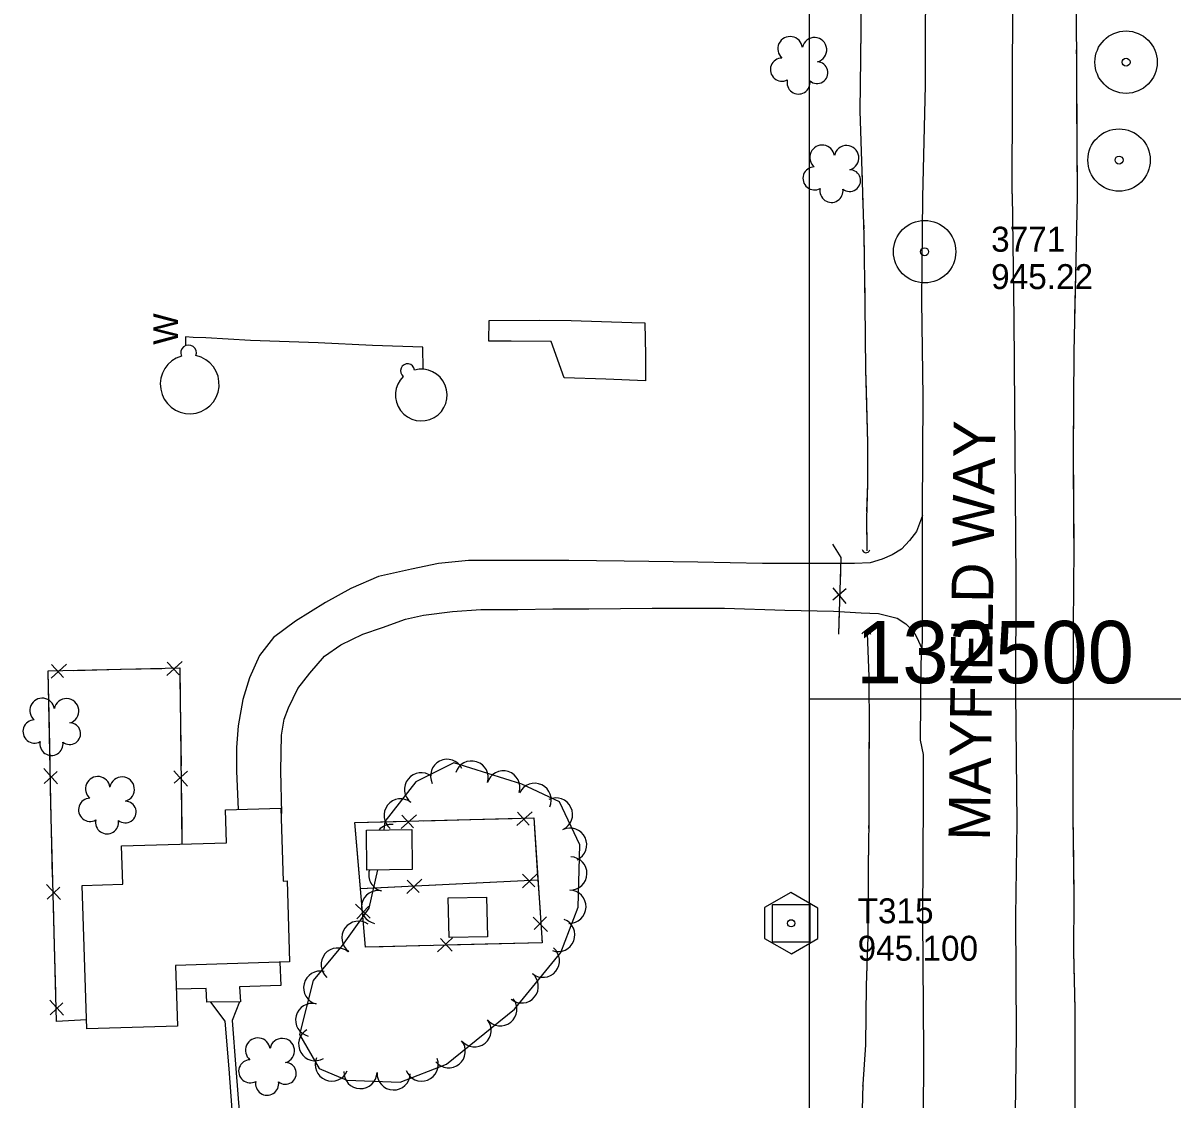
# Model space of a CAD drawing. Extents: x 353423 to 364002, y 127000 to 201942.
# Drawn here: x 359810.7 to 360087.2, y 132403.7 to 132662.6 of the extents above; entities that cross this region are included whole.
import ezdxf

# ---------------------------------------------------------------- set-up
doc = ezdxf.new("R2010")
doc.units = 0
for name, color, linetype in [('E_BMGRD', 7, 'Continuous'), ('E_DTM_SlopeBottom', 7, 'Continuous'), ('E_DTM_SlopeTop', 7, 'Continuous'), ('E_FEN_Generic', 7, 'Continuous'), ('E_LAND_TreeLine', 7, 'Continuous'), ('E_MISCPROP', 7, 'Continuous'), ('E_RDWY_AsphConc', 7, 'Continuous'), ('E_RW_IP', 7, 'Continuous'), ('E_STRUCT_WingWall', 7, 'Continuous'), ('E_WTR_FlowLine', 7, 'Continuous')]:
    doc.layers.add(name, color=color, linetype=linetype)

msp = doc.modelspace()

# ---------------------------------------------------------------- linework, layer by layer
at = {"layer": 'E_BMGRD'}
for points in [[(359989.15, 132449.77), (359989.15, 132442.38), (359995.61, 132438.65), (360002, 132442.32), (360002, 132449.65), (359995.48, 132453.38)], [(359989.15, 132449.77), (359989.15, 132442.38), (359995.61, 132438.65), (360002, 132442.32), (360002, 132449.65), (359995.48, 132453.38)], [(359991.06, 132441.51), (359991.06, 132450.51), (360000.06, 132450.51), (360000.06, 132441.51)], [(359991.06, 132441.51), (359991.06, 132450.51), (360000.06, 132450.51), (360000.06, 132441.51)]]:
    msp.add_lwpolyline(points, close=True, dxfattribs=at)
msp.add_circle((359995.56, 132446.01), 0.871, dxfattribs=at)
msp.add_circle((359995.56, 132446.01), 0.871, dxfattribs=at)
at = {"layer": 'E_DTM_SlopeBottom'}
for p, q in [((360008.81, 132526.48), (360005.56, 132523.78)), ((360005.58, 132526.75), (360008.71, 132522.94)), ((359845.31, 132505.62), (359848.95, 132508.95)), ((359845.4, 132508.86), (359848.27, 132505.76)), ((359817.45, 132504.99), (359821.1, 132508.31)), ((359817.55, 132508.23), (359820.42, 132505.13)), ((359819, 132479.57), (359815.69, 132483.23)), ((359815.76, 132479.68), (359818.87, 132482.54)), ((359846.98, 132482.7), (359850.26, 132479.02)), ((359850.22, 132482.57), (359847.08, 132479.74)), ((359929.57, 132469.51), (359933.21, 132472.84)), ((359929.66, 132472.75), (359932.54, 132469.65)), ((359901.72, 132468.8), (359905.36, 132472.13)), ((359901.81, 132472.04), (359904.69, 132468.94)), ((359903.09, 132453.18), (359906.64, 132456.6)), ((359903.1, 132456.42), (359906.05, 132453.39)), ((359930.92, 132454.57), (359934.47, 132457.99)), ((359930.92, 132457.81), (359933.88, 132454.79)), ((359819.68, 132451.73), (359816.35, 132455.36)), ((359816.44, 132451.82), (359819.54, 132454.7)), ((359894.25, 132447.22), (359890.71, 132450.65)), ((359891, 132447.11), (359893.93, 132450.17)), ((359933.46, 132447.5), (359936.94, 132444.01)), ((359936.7, 132447.55), (359933.72, 132444.54)), ((359914.08, 132442.51), (359910.44, 132439.18)), ((359913.99, 132439.27), (359911.12, 132442.37)), ((359820.43, 132423.88), (359817.09, 132427.51)), ((359817.19, 132423.97), (359820.28, 132426.85))]:
    msp.add_line(p, q, dxfattribs=at)
for points in [[(359906.97, 132579.3), (359906.89, 132584.63), (359894.82, 132584.98), (359881.74, 132585.62), (359865.39, 132586.24), (359854.71, 132586.86), (359851.59, 132586.95), (359849.81, 132587.08), (359849.79, 132584.98)], [(360005.54, 132537.25), (360007.52, 132533.99), (360007, 132515.56)], [(360005.54, 132537.25), (360007.52, 132533.99), (360007.35, 132527.86)], [(360007.16, 132521.28), (360007, 132515.56)], [(359825.94, 132422.8), (359818.73, 132422.42), (359817.42, 132471.48), (359816.74, 132506.71), (359848.41, 132507.43), (359848.93, 132465.06)], [(359816.94, 132496.28), (359816.74, 132506.23)], [(359822.84, 132506.85), (359834.15, 132507.11)], [(359834.15, 132507.11), (359844.11, 132507.34)], [(359848.44, 132505.16), (359848.58, 132493.84)], [(359817.16, 132484.96), (359816.94, 132496.28)], [(359848.58, 132493.84), (359848.7, 132483.88)], [(359817.5, 132468.42), (359817.42, 132471.48), (359817.28, 132478.38)], [(359848.78, 132477.3), (359848.92, 132465.98)], [(359890.57, 132470.25), (359900.52, 132470.51)], [(359891.11, 132463.75), (359890.57, 132470.25)], [(359907.1, 132470.67), (359918.42, 132470.96)], [(359918.42, 132470.96), (359928.37, 132471.21)], [(359933.69, 132470), (359934.45, 132458.71)], [(359817.8, 132457.11), (359817.5, 132468.42)], [(359848.92, 132465.98), (359848.93, 132465.06)], [(359892.06, 132452.47), (359891.11, 132463.75)], [(359934.45, 132458.71), (359935.11, 132448.77)], [(359891.9, 132454.36), (359934.6, 132456.49)], [(359919.73, 132455.75), (359929.67, 132456.25)], [(359891.9, 132454.36), (359901.85, 132454.86)], [(359908.42, 132455.18), (359919.73, 132455.75)], [(359818.24, 132440.58), (359817.98, 132450.53)], [(359897.38, 132440.38), (359893.08, 132440.28), (359892.61, 132445.91)], [(359935.55, 132442.21), (359935.62, 132441.27), (359925.24, 132441.03)], [(359818.54, 132429.26), (359818.24, 132440.58)], [(359908.7, 132440.64), (359897.38, 132440.38)], [(359925.24, 132441.03), (359915.28, 132440.8)], [(359825.94, 132422.8), (359818.73, 132422.42), (359818.72, 132422.68)]]:
    msp.add_lwpolyline(points, dxfattribs=at)
msp.add_lwpolyline([(359890.57, 132470.25), (359933.6, 132471.35), (359935.62, 132441.27), (359893.08, 132440.28)], close=True, dxfattribs=at)
for centre, major_axis, ratio, start_param, end_param in [((360013.64, 132536.92), (-0.1, -1.75), 0.679612, 5.356084, 7.210314), ((360013.59, 132514.61), (0.1, 1.6), 0.86561, 5.356056, 7.210287)]:
    msp.add_ellipse(centre, major_axis=major_axis, ratio=ratio, start_param=start_param, end_param=end_param, dxfattribs=at)
at = {"layer": 'E_DTM_SlopeTop'}
for points in [[(360048.78, 132621.5), (360048.89, 132669.64), (360049.35, 132727.67), (360049.55, 132793.59), (360049.56, 132842.31), (360049.06, 132893.44), (360046.96, 132939.69), (360042.98, 132986.33), (360039.67, 133020.54), (360037.17, 133037.76), (360034.31, 133052.24), (360029.63, 133066.98), (360021.41, 133087.08), (360018.16, 133096.99), (360017.7, 133101.52), (360017.78, 133107.23), (360018.75, 133112.13), (360021.8, 133117.95), (360028.18, 133126.37), (360033.76, 133132.81), (360043.26, 133140.02), (360051.73, 133145.18), (360065.4, 133153.61), (360076.88, 133160.45)], [(360027.23, 132620.67), (360027.87, 132647.58), (360028.02, 132681.7), (360027.8, 132714.79), (360027.51, 132749.37), (360027.39, 132782.59), (360027.41, 132815.67), (360026.89, 132839.13), (360026.59, 132870.23), (360026.04, 132895.36), (360025.34, 132920.28), (360024.14, 132942.78), (360021.99, 132971.11), (360019.71, 132995.27), (360017.64, 133014.91), (360015.47, 133028.73), (360012.35, 133042.68), (360009.28, 133055.39), (360004.06, 133065.39), (359997.75, 133072.22), (359991.54, 133078.73), (359986.24, 133082.79), (359979.5, 133085.97), (359972.18, 133088.23)], [(360048.78, 132621.5), (360049.18, 132591.44), (360049.39, 132559.26), (360049.66, 132528.75), (360049.6, 132501.34), (360049.88, 132470.2), (360049.59, 132447.73), (360049.71, 132419.23), (360049.38, 132393.96), (360049.03, 132375.17), (360048.88, 132349.14), (360048.96, 132325.03), (360048.95, 132303.55), (360048.95, 132297.74), (360049.36, 132294.76), (360049.76, 132287.27), (360050.44, 132273.42), (360051.26, 132262.99), (360051.68, 132254.79), (360051.73, 132247.93), (360051.14, 132246.45), (360038.64, 132246.23), (360027.18, 132245.86), (360014.77, 132244.52)], [(360016.25, 132267.67), (360020.08, 132271.23), (360022.29, 132274.05), (360024.15, 132277.42), (360025.73, 132281.42), (360026.38, 132286.29), (360026.87, 132293.05), (360026.74, 132307.01), (360026.9, 132325.22), (360027.14, 132349.95), (360027.36, 132381.33), (360027.52, 132415.08), (360027.26, 132447.06), (360027.42, 132476.38), (360027.43, 132486.58), (360026.74, 132490.03), (360026.87, 132508.62), (360027.2, 132514), (360027.22, 132539.86), (360027.21, 132545.21), (360027.35, 132572.62), (360027.03, 132595.73), (360027.23, 132620.67)]]:
    msp.add_lwpolyline(points, dxfattribs=at)
at = {"layer": 'E_FEN_Generic'}
msp.add_lwpolyline([(359895.98, 132458.85), (359893.92, 132449.65), (359887.49, 132440.64), (359880.47, 132432.24), (359877.24, 132419.26), (359881.95, 132411.07), (359888.6, 132408.26), (359901.44, 132407.78), (359912.62, 132412.11), (359928.94, 132425.38), (359940.14, 132438.96), (359944.28, 132449.88), (359944.69, 132464.86), (359939.84, 132475.19), (359930.72, 132479.48), (359914.34, 132484.62), (359905.21, 132480.01), (359897.74, 132470.5), (359897.48, 132468.46)], dxfattribs=at)
for centre, radius, start, end in [((359995.32, 132656.37), 2.97, 7.0782, 228.3121), ((360001.16, 132656.12), 2.97, 284.7291, 167.7023), ((359993.34, 132651.37), 2.78, 90.0491, 297.8221), ((360001.8, 132650.64), 2.61, 229.4343, 87.3669), ((359997.35, 132648.28), 2.78, 166.7261, 7.7372), ((360003.04, 132630.25), 2.97, 8.541, 229.7749), ((360008.89, 132630.15), 2.97, 286.1918, 169.1651), ((360001.19, 132625.2), 2.78, 91.5119, 299.2849), ((360009.67, 132624.68), 2.61, 230.8971, 88.8297), ((360005.27, 132622.21), 2.78, 168.1889, 9.2), ((359815.28, 132497.19), 2.97, 8.541, 229.7749), ((359821.13, 132497.09), 2.97, 286.1918, 169.1651), ((359813.43, 132492.14), 2.78, 91.5119, 299.2849), ((359821.91, 132491.62), 2.61, 230.8971, 88.8297), ((359817.51, 132489.15), 2.78, 168.1889, 9.2), ((359912.76, 132481.48), 4, 26.8175, 206.8022), ((359918.65, 132481.07), 4, 342.5854, 162.5701), ((359828.66, 132478.35), 2.97, 8.541, 229.7749), ((359834.51, 132478.25), 2.97, 286.1918, 169.1651), ((359906.49, 132478.25), 4, 51.875, 231.8597), ((359926.28, 132478.68), 4, 342.5854, 162.5701), ((359933.83, 132475.7), 4, 334.789, 154.7737), ((359826.81, 132473.3), 2.78, 91.5119, 299.2849), ((359835.29, 132472.78), 2.61, 230.8971, 88.8297), ((359901.55, 132471.96), 4, 51.875, 231.8597), ((359938.94, 132472.17), 4, 295.1902, 115.1748), ((359830.89, 132470.31), 2.78, 168.1889, 9.2), ((359899.25, 132465.77), 4, 82.7489, 138.0617), ((359942.35, 132464.93), 4, 295.1902, 115.1748), ((359942.41, 132457.99), 4, 268.412, 88.3967), ((359897.87, 132457.7), 4, 163.7157, 257.3673), ((359896.12, 132449.89), 4, 77.3827, 257.3673), ((359942.19, 132449.99), 4, 268.412, 88.3967), ((359891.4, 132442.51), 4, 54.4747, 234.4594), ((359939.5, 132443.19), 4, 249.2315, 69.2162), ((359886.4, 132436.07), 4, 50.1047, 230.0894), ((359935.81, 132437), 4, 230.5166, 50.5013), ((359882.19, 132430.51), 4, 76.0696, 256.0543), ((359930.72, 132430.83), 4, 230.5166, 50.5013), ((359880.27, 132422.75), 4, 76.0696, 256.0543), ((359925.55, 132425.32), 4, 219.1101, 39.0948), ((359919.35, 132420.28), 4, 219.1101, 39.0948), ((359880.99, 132416.94), 4, 119.9124, 299.897), ((359867.2, 132415.45), 2.97, 8.541, 229.7749), ((359873.05, 132415.35), 2.97, 286.1918, 169.1651), ((359913.14, 132415.23), 4, 219.1101, 39.0948), ((359865.35, 132410.41), 2.78, 91.5119, 299.2849), ((359873.83, 132409.89), 2.61, 230.8971, 88.8297), ((359885.01, 132412.05), 4, 157.0879, 337.0726), ((359906.62, 132412.03), 4, 201.1955, 21.1802), ((359891.89, 132410.23), 4, 177.8666, 357.8513), ((359899.88, 132409.93), 4, 177.8666, 357.8513), ((359869.43, 132407.42), 2.78, 168.1889, 9.2)]:
    msp.add_arc(centre, radius, start, end, dxfattribs=at)
at = {"layer": 'E_LAND_TreeLine'}
for p, q in [((360000, 132500), (360000, 135000)), ((360000, 131000), (360000, 133500)), ((360000, 132500), (364000, 132500)), ((360000, 132500), (364000, 132500))]:
    msp.add_line(p, q, dxfattribs=at)
at = {"layer": 'E_MISCPROP'}
msp.add_lwpolyline([(359922.85, 132591.04), (359934.98, 132591.08), (359942.61, 132590.99), (359957.19, 132590.56), (359960.36, 132590.47), (359960.5, 132582.68), (359960.54, 132576.5), (359950.98, 132576.88), (359940.96, 132577.21), (359937.77, 132585.98), (359928.14, 132586.03), (359922.8, 132586.08)], close=True, dxfattribs=at)
for points in [[(360027.21, 132544.15), (360025.72, 132540.27), (360024.03, 132538.12), (360022.11, 132536.02), (360019.87, 132534.65), (360017.47, 132533.57), (360014.56, 132532.76), (360010.78, 132532.58), (360001.54, 132532.57), (359988.68, 132532.6), (359973.1, 132532.87), (359955.35, 132533.12), (359942.04, 132533.26), (359927.13, 132533.31), (359917.89, 132533.3), (359910.7, 132532.6), (359904.17, 132531.22), (359896.2, 132529.47), (359889.54, 132526.53), (359883.49, 132523.2), (359876.27, 132518.71), (359870.93, 132514.77), (359867.6, 132510.4), (359865.21, 132505.09), (359863.54, 132499.82), (359862.47, 132493.54), (359862.03, 132488.31), (359862.08, 132482.58), (359862.49, 132473.39)], [(359872.77, 132472.44), (359872.93, 132472.44), (359872.71, 132482.69), (359872.91, 132491.26), (359873.51, 132495.14), (359874.6, 132497.86), (359876.82, 132502.51), (359879.69, 132506.21), (359883.24, 132510.24), (359887.17, 132513.03), (359892.43, 132515.59), (359897.18, 132517.16), (359902.71, 132519.16), (359907.06, 132520.11), (359914.03, 132521.04), (359920.88, 132521.47), (359929.78, 132521.48), (359938.19, 132521.67), (359946.87, 132521.63), (359962.07, 132521.86), (359979.55, 132521.78), (359994.01, 132521.35), (360005.75, 132521.06), (360012.43, 132520.71), (360016.55, 132520.55), (360019.49, 132519.85), (360021.1, 132519.39), (360023.14, 132518.03), (360024.96, 132516.34), (360025.73, 132514.89), (360027.08, 132511.97)], [(359855.78, 132427.05), (359859.25, 132422.49), (359860.18, 132410.96), (359861.45, 132394.52), (359862.79, 132379.2), (359863.73, 132368.16), (359866.43, 132339.7), (359867.78, 132319.83), (359869, 132304.16), (359869.99, 132292.85)], [(359862.81, 132427.12), (359860.99, 132422.63), (359861.93, 132411.1), (359863.2, 132394.67), (359864.54, 132379.35), (359865.48, 132368.32), (359868.18, 132339.85), (359869.52, 132319.96), (359870.75, 132304.31), (359871.74, 132293), (359869.99, 132292.85)]]:
    msp.add_lwpolyline(points, dxfattribs=at)
at = {"layer": 'E_RDWY_AsphConc'}
for centre, radius in [((360076.18, 132653.17), 7.5), ((360076.18, 132653.17), 7.5), ((360076.18, 132653.17), 7.5), ((360076.18, 132653.17), 7.5), ((360076.18, 132653.17), 0.96), ((360076.18, 132653.17), 0.96), ((360076.18, 132653.17), 0.96), ((360076.18, 132653.17), 0.96), ((360074.49, 132629.62), 7.5), ((360074.49, 132629.62), 7.5), ((360074.49, 132629.62), 7.5), ((360074.49, 132629.62), 7.5), ((360074.49, 132629.62), 0.96), ((360074.49, 132629.62), 0.96), ((360074.49, 132629.62), 0.96), ((360074.49, 132629.62), 0.96), ((360027.7, 132607.58), 7.5), ((360027.7, 132607.58), 7.5), ((360027.7, 132607.58), 7.5), ((360027.7, 132607.58), 7.5), ((360027.7, 132607.58), 0.96), ((360027.7, 132607.58), 0.96), ((360027.7, 132607.58), 0.96), ((360027.7, 132607.58), 0.96)]:
    msp.add_circle(centre, radius, dxfattribs=at)
at = {"layer": 'E_STRUCT_WingWall'}
for points in [[(360051.39, 133014.2), (360054.61, 132988.82), (360058.66, 132962.03), (360061.59, 132936.26), (360063.66, 132910.59), (360066.07, 132883.05), (360065.52, 132865.84), (360064.1, 132839.25), (360063.99, 132811.88), (360063.85, 132787.4), (360064.64, 132759.1), (360065.16, 132728.41), (360064.81, 132695.07), (360064.14, 132665.48), (360064.43, 132620.95)], [(360005.24, 133011.35), (360006.89, 132997.82), (360007.31, 132980.78), (360009.13, 132961.68), (360009.19, 132942.55), (360010.58, 132920.75), (360010.91, 132901.51), (360010.66, 132883.98), (360010.94, 132865.29), (360011.6, 132848.74), (360011.43, 132826.09), (360011.62, 132802.05), (360012.11, 132782.53), (360012.39, 132757.06), (360012.52, 132732.86), (360012.19, 132713.46), (360012.27, 132695.99), (360012.48, 132676.25), (360012.25, 132654.02)], [(360064.16, 132662.13), (360064.18, 132660.13)], [(360012.3, 132658.62), (360012.28, 132656.62)], [(360064.2, 132656.13), (360064.22, 132654.13)], [(360012.25, 132654.02), (360012.11, 132641.5), (360012.57, 132626.86), (360013.07, 132611.55), (360013.34, 132594.9), (360013.45, 132579.21), (360013.98, 132561.61), (360013.94, 132551.76), (360013.68, 132543.3), (360013.82, 132535.62)], [(360012.25, 132654.02), (360012.11, 132641.5), (360012.57, 132626.86), (360012.63, 132625.03)], [(360064.24, 132650.13), (360064.26, 132648.13)], [(360064.28, 132644.13), (360064.43, 132620.95)], [(360012.76, 132621.04), (360012.83, 132619.04)], [(360064.43, 132620.95), (360064.06, 132605.62), (360063.61, 132583.41), (360063.41, 132559.85), (360063.59, 132536.23), (360063.41, 132517.64), (360063.45, 132499.42), (360063.34, 132485.64), (360063.35, 132471.81), (360063.64, 132452.08), (360063.51, 132439.25), (360063.85, 132425.41), (360063.84, 132413.75), (360063.84, 132399.76)], [(360064.43, 132620.95), (360064.06, 132605.62), (360063.78, 132591.96)], [(360012.96, 132615.04), (360013.02, 132613.04)], [(360013.11, 132609.04), (360013.15, 132607.04)], [(360013.21, 132603.04), (360013.34, 132594.9), (360013.45, 132579.21), (360013.61, 132574.05)], [(360063.7, 132587.96), (360063.66, 132585.96)], [(360063.59, 132581.96), (360063.58, 132579.96)], [(360063.54, 132575.96), (360063.53, 132573.96)], [(360013.61, 132574.05), (360013.98, 132561.61), (360013.94, 132551.76), (360013.73, 132545.05)], [(360063.49, 132569.96), (360063.41, 132559.85), (360063.55, 132540.96)], [(360013.72, 132541.06), (360013.76, 132539.06)], [(360063.55, 132540.96), (360063.59, 132536.23), (360063.41, 132517.64), (360063.42, 132511.96)], [(360013.89, 132515.8), (360014.27, 132505.34), (360014.36, 132492.48), (360014.26, 132483.46), (360014.23, 132470.44), (360014.12, 132459.81), (360014.05, 132442.72), (360013.59, 132431.04), (360013.44, 132416.74), (360012.78, 132407.33), (360012.45, 132391.98), (360012.29, 132377.06), (360012.19, 132362.42), (360012.16, 132349.85), (360012.04, 132338.71), (360012.03, 132327.3), (360012.37, 132317), (360012.41, 132305.43), (360012.87, 132296.24), (360012.96, 132288.78), (360012.8, 132284.66), (360012.14, 132280.49), (360010.09, 132275.73)], [(360013.89, 132515.8), (360014.27, 132505.34), (360014.36, 132492.48), (360014.3, 132486.81)], [(360063.43, 132507.96), (360063.44, 132505.96)], [(360063.45, 132501.96), (360063.45, 132499.96)], [(360063.42, 132495.96), (360063.41, 132493.96)], [(360063.37, 132489.96), (360063.34, 132485.64), (360063.35, 132471.81), (360063.51, 132460.96)], [(360014.26, 132482.81), (360014.26, 132480.81)], [(360014.25, 132476.81), (360014.24, 132474.81)], [(360014.23, 132470.81), (360014.23, 132470.44), (360014.22, 132468.81)], [(360014.17, 132464.81), (360014.12, 132459.81), (360014.05, 132442.72), (360013.78, 132435.82)], [(360063.51, 132460.96), (360063.64, 132452.08), (360063.51, 132439.25), (360063.69, 132431.97)], [(360013.78, 132435.82), (360013.59, 132431.04), (360013.44, 132416.74), (360012.78, 132407.33), (360012.77, 132406.85)], [(360063.79, 132427.97), (360063.84, 132425.97)], [(360063.85, 132421.97), (360063.84, 132419.97)], [(360063.84, 132415.97), (360063.84, 132413.97)], [(360063.84, 132409.97), (360063.84, 132399.76), (360063.96, 132385.42), (360064.03, 132380.97)]]:
    msp.add_lwpolyline(points, dxfattribs=at)
at = {"layer": 'E_WTR_FlowLine'}
for points in [[(359834.39, 132464.61), (359859.67, 132465.39), (359859.42, 132473.3), (359872.73, 132473.71), (359873.28, 132456.18), (359874.21, 132456.21), (359874.81, 132436.73), (359847.37, 132435.87), (359847.82, 132421.27), (359826.01, 132420.59), (359824.93, 132455.08), (359834.68, 132455.39)], [(359904.36, 132458.97), (359893.45, 132458.81), (359893.31, 132468.39), (359904.22, 132468.56)], [(359913.03, 132452.14), (359922.27, 132452.32), (359922.45, 132442.75), (359913.21, 132442.57)]]:
    msp.add_lwpolyline(points, close=True, dxfattribs=at)
msp.add_lwpolyline([(359872.49, 132436.66), (359872.72, 132431.02), (359862.75, 132430.74), (359862.99, 132427.12), (359854.92, 132427.04), (359854.79, 132430.33), (359847.55, 132430.16)], dxfattribs=at)
for centre, major_axis, ratio, start_param, end_param in [((359850.51, 132583.23), (1.84, -0.43), 0.999838, 6.168164, 10.070195), ((359850.79, 132575.67), (5.54, 4.41), 0.999975, 1.185112, 6.967706), ((359903.21, 132578.92), (-0.73, 1.52), 0.999955, 4.367998, 8.341355), ((359906.54, 132573.09), (6.15, 0.99), 0.999841, 2.179739, 7.964235)]:
    msp.add_ellipse(centre, major_axis=major_axis, ratio=ratio, start_param=start_param, end_param=end_param, dxfattribs=at)

# ---------------------------------------------------------------- texts
at = {"layer": 'E_BMGRD'}
for s, p in [('T315', (360011.56, 132446.01)), ('T315', (360011.56, 132446.01)), ('945.100', (360011.56, 132437.01)), ('945.100', (360011.56, 132437.01))]:
    msp.add_text(s, height=6, dxfattribs=at).set_placement(p)
at = {"layer": 'E_DTM_SlopeBottom'}
msp.add_text('W', height=6, rotation=90.1181, dxfattribs=at).set_placement((359848.01, 132585.2))
at = {"layer": 'E_LAND_TreeLine'}
msp.add_text('  132500  ', height=15, dxfattribs=at).set_placement((360000, 132503.75))
at = {"layer": 'E_RDWY_AsphConc'}
for s, p in [('3771', (360043.7, 132607.58)), ('3771', (360043.7, 132607.58)), ('3771', (360043.7, 132607.58)), ('3771', (360043.7, 132607.58)), ('945.22', (360043.7, 132598.58)), ('945.22', (360043.7, 132598.58)), ('945.22', (360043.7, 132598.58)), ('945.22', (360043.7, 132598.58))]:
    msp.add_text(s, height=6, dxfattribs=at).set_placement(p)
at = {"layer": 'E_RW_IP'}
msp.add_text('MAYFIELD WAY', height=10, rotation=89.2586, dxfattribs=at).set_placement((360043.42, 132465.85))

doc.saveas('drawing.dxf')
